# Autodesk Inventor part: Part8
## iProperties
Created: 2002-04
Part Number: Part8
Document SubType Name: Sheet Metal
Control State: 0
Master: False
Checked Out: False
Shininess: 77.0
Angle Display Precision: 2
Document Length Units: 11269
Document Angle Units: 11279
Document Time Units: 11290
Document Mass Units: 11283
Document Length Units Precision: 3
Document Angle Units Precision: 2
Compacted: True
Density: 0.0
Volumn: 0.0
Area: 0.0
PropertySet Name: Model Information
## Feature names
1. Plate1
2. Plate3
3. Bend2
